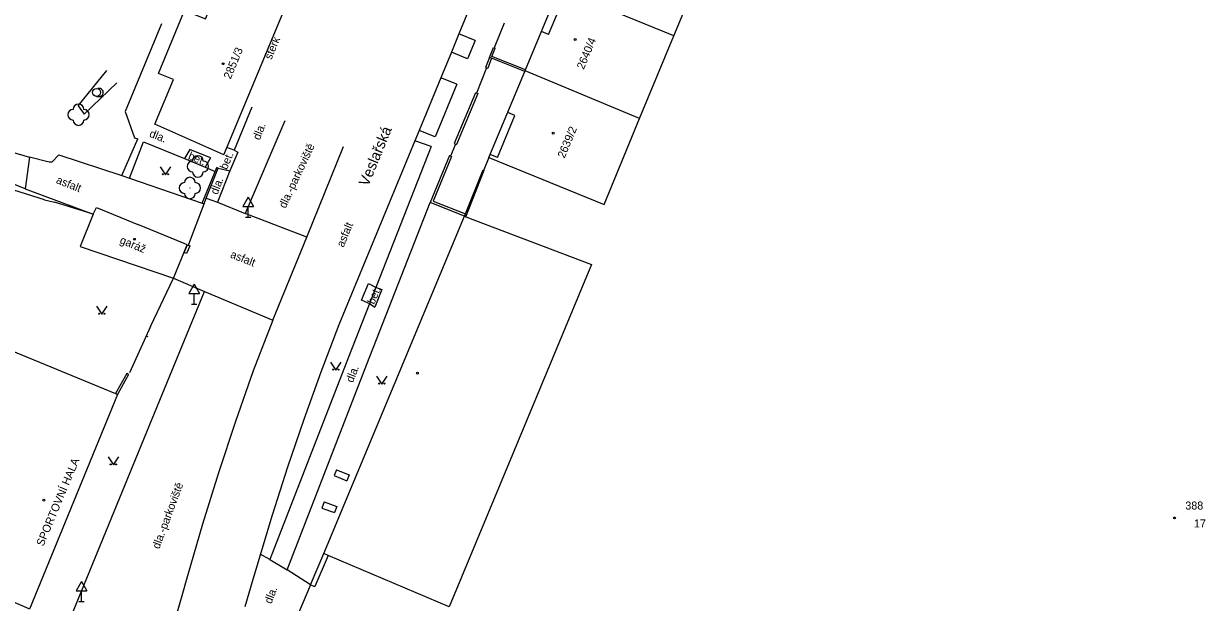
# Model space of a CAD drawing. Extents: x -584400 to -581602, y -1210894 to -1208793.
# Drawn here: x -583374.3 to -583263.6, y -1210749.1 to -1210695 of the extents above; entities that cross this region are included whole.
import ezdxf

# ---------------------------------------------------------------- set-up
doc = ezdxf.new("R2010")
doc.units = 0
for name, color, linetype in [('BUDOVY_MĚŘ', 7, 'Continuous'), ('BUDOVY_NEMĚŘ', 7, 'Continuous'), ('NÁZVY_ULIC_TOK_SMĚR', 7, 'Continuous'), ('OBVOD_PILÍŘE', 7, 'Continuous'), ('POMOC_POPIS', 7, 'Continuous'), ('ROZHRANÍ_PLOCH', 7, 'Continuous'), ('ZELEŇ', 7, 'Continuous'), ('ZN_BUDOV', 7, 'Continuous'), ('ZN_DOPLŇKOVÉ', 7, 'Continuous'), ('ZN_KULTUR', 7, 'Continuous'), ('Č_POPIS_EVID', 7, 'Continuous'), ('Č_POPIS_ORIENT', 7, 'Continuous')]:
    doc.layers.add(name, color=color, linetype=linetype)

msp = doc.modelspace()

# ---------------------------------------------------------------- linework, layer by layer
at = {"layer": 'BUDOVY_MĚŘ'}
for points in [[(-583355.51, -1210707.24), (-583348.87, -1210691.26), (-583344.69, -1210681.25), (-583344.47, -1210680.69)], [(-583327.29, -1210699.37), (-583327.26, -1210699.29), (-583324.17, -1210691.83), (-583324.11, -1210691.69)], [(-583330.68, -1210707.48), (-583327.32, -1210699.45), (-583327.29, -1210699.37)], [(-583419.13, -1210730.56), (-583417.5, -1210726.74), (-583423.55, -1210724.2), (-583417.13, -1210708.39), (-583365.65, -1210729.57), (-583365.46, -1210729.65), (-583373.7, -1210749.74), (-583373.97, -1210749.63), (-583381.84, -1210746.3), (-583382.08, -1210746.2), (-583419.13, -1210730.56)], [(-583367.74, -1210712.78), (-583367.44, -1210712.17), (-583363.58, -1210713.76)], [(-583360.23, -1210718.77), (-583358.95, -1210715.66), (-583359.23, -1210715.54), (-583363.58, -1210713.76)], [(-583345.74, -1210744.73), (-583346.15, -1210744.56), (-583332.96, -1210712.98), (-583332.85, -1210713.03)]]:
    msp.add_lwpolyline(points, dxfattribs=at)
at = {"layer": 'BUDOVY_NEMĚŘ'}
for points in [[(-583313.35, -1210696.1), (-583310.15, -1210688.36)], [(-583355.51, -1210707.24), (-583361.99, -1210704.37), (-583360.23, -1210700.2), (-583361.62, -1210699.63), (-583359.19, -1210693.72), (-583357.24, -1210694.52), (-583354.98, -1210689.24), (-583353.8, -1210689.63), (-583348.87, -1210691.26)], [(-583316.56, -1210703.85), (-583313.35, -1210696.1), (-583324.11, -1210691.69)], [(-583330.68, -1210707.48), (-583319.89, -1210711.89), (-583316.56, -1210703.85), (-583327.29, -1210699.37)], [(-583367.74, -1210712.78), (-583368.97, -1210715.81)], [(-583332.85, -1210713.03), (-583321.06, -1210717.51), (-583334.41, -1210749.53), (-583345.74, -1210744.73)], [(-583368.97, -1210715.81), (-583360.23, -1210718.77)]]:
    msp.add_lwpolyline(points, dxfattribs=at)
at = {"layer": 'OBVOD_PILÍŘE'}
msp.add_lwpolyline([(-583358.85, -1210716.12), (-583359, -1210716.48), (-583359.23, -1210716.39), (-583358.93, -1210715.66), (-583358.7, -1210715.76), (-583358.85, -1210716.12)], dxfattribs=at)
at = {"layer": 'ROZHRANÍ_PLOCH'}
for points in [[(-583325.09, -1210695.98), (-583323.48, -1210692.12), (-583324.17, -1210691.83)], [(-583332.43, -1210693.34), (-583333.5, -1210695.91)], [(-583361.34, -1210694.97), (-583364.76, -1210703.17)], [(-583333.5, -1210695.91), (-583334.19, -1210697.63)], [(-583331.98, -1210696.54), (-583333.5, -1210695.91)], [(-583325.09, -1210695.98), (-583325.76, -1210695.7)], [(-583331.98, -1210696.54), (-583332.69, -1210698.25), (-583334.19, -1210697.63)], [(-583334.19, -1210697.63), (-583335.19, -1210700.04)], [(-583335.19, -1210700.04), (-583337.2, -1210704.95)], [(-583333.67, -1210700.62), (-583335.19, -1210700.04)], [(-583333.67, -1210700.62), (-583335.71, -1210705.56), (-583337.2, -1210704.95)], [(-583352.89, -1210702.77), (-583354.55, -1210706.81)], [(-583364.76, -1210703.17), (-583363.89, -1210705.64)], [(-583329.89, -1210707.49), (-583328.25, -1210703.56), (-583328.92, -1210703.27)], [(-583349.79, -1210704.05), (-583353.52, -1210712.74)], [(-583337.2, -1210704.95), (-583337.61, -1210705.94)], [(-583381, -1210705.33), (-583373.71, -1210707.44)], [(-583365.07, -1210709.18), (-583363.58, -1210705.73)], [(-583364.36, -1210709.42), (-583363.03, -1210706.03)], [(-583363.89, -1210705.64), (-583363.58, -1210705.73)], [(-583363.03, -1210706.03), (-583359.2, -1210707.59)], [(-583337.61, -1210705.94), (-583344.73, -1210723.16), (-583346.41, -1210727.57), (-583348.01, -1210732.01), (-583349.54, -1210736.48), (-583350.99, -1210740.97), (-583352.8, -1210746.97), (-583353.54, -1210749.55)], [(-583336.08, -1210706.45), (-583337.61, -1210705.94)], [(-583370.98, -1210707.24), (-583371.62, -1210707.91)], [(-583370.98, -1210707.24), (-583365.07, -1210709.18)], [(-583358.69, -1210706.73), (-583359.2, -1210707.59)], [(-583356.75, -1210707.52), (-583358.69, -1210706.73)], [(-583354.55, -1210706.81), (-583355.23, -1210706.56)], [(-583354.19, -1210706.99), (-583354.95, -1210708.73)], [(-583354.55, -1210706.81), (-583354.19, -1210706.99)], [(-583336.08, -1210706.45), (-583343.82, -1210726.18), (-583351.19, -1210745.1)], [(-583347.74, -1210714.95), (-583344.3, -1210706.45)], [(-583329.89, -1210707.49), (-583330.56, -1210707.21)], [(-583374.12, -1210710.42), (-583381.47, -1210707.44)], [(-583373.71, -1210707.44), (-583374.12, -1210710.42)], [(-583371.87, -1210707.91), (-583373.71, -1210707.44)], [(-583371.62, -1210707.91), (-583371.87, -1210707.91)], [(-583359.2, -1210707.59), (-583357.26, -1210708.38)], [(-583356.75, -1210707.52), (-583357.26, -1210708.38)], [(-583365.07, -1210709.18), (-583364.36, -1210709.42)], [(-583364.36, -1210709.42), (-583357.54, -1210711.76), (-583357.34, -1210711.83)], [(-583357.26, -1210708.38), (-583356.32, -1210708.81)], [(-583354.95, -1210708.73), (-583356.12, -1210711.67)], [(-583356.03, -1210708.49), (-583354.95, -1210708.73)], [(-583374.12, -1210710.42), (-583367.74, -1210712.78)], [(-583357.18, -1210711.29), (-583356.12, -1210711.67)], [(-583356.12, -1210711.67), (-583353.52, -1210712.74)], [(-583347.74, -1210714.95), (-583353.52, -1210712.74)], [(-583349.58, -1210746.08), (-583342.1, -1210726.84), (-583336.19, -1210711.7)], [(-583350.91, -1210722.71), (-583347.74, -1210714.95)], [(-583360.23, -1210718.77), (-583357.31, -1210720.03)], [(-583342.62, -1210720.85), (-583341.97, -1210719.27)], [(-583341.97, -1210719.27), (-583341.31, -1210719.61)], [(-583362.21, -1210731.95), (-583357.31, -1210720.03)], [(-583357.31, -1210720.03), (-583350.91, -1210722.71)], [(-583340.7, -1210719.83), (-583341.36, -1210721.5)], [(-583341.31, -1210719.61), (-583340.7, -1210719.83)], [(-583341.78, -1210721.2), (-583342.62, -1210720.85)], [(-583341.78, -1210721.2), (-583341.36, -1210721.5)], [(-583350.91, -1210722.71), (-583352.77, -1210727.44), (-583354.43, -1210732.2), (-583356, -1210736.99), (-583357.5, -1210741.8), (-583358.93, -1210746.63), (-583360.15, -1210751.03)], [(-583370.13, -1210751.2), (-583362.21, -1210731.95)], [(-583344.96, -1210736.7), (-583345.19, -1210737.25), (-583343.99, -1210737.74)], [(-583344.96, -1210736.7), (-583343.76, -1210737.18), (-583343.99, -1210737.74)], [(-583346.12, -1210739.72), (-583346.33, -1210740.29), (-583345.15, -1210740.72)], [(-583346.12, -1210739.72), (-583344.94, -1210740.16), (-583345.15, -1210740.72)], [(-583351.19, -1210745.1), (-583352.1, -1210744.61)], [(-583351.19, -1210745.1), (-583349.58, -1210746.08)], [(-583347.4, -1210747.47), (-583349.58, -1210746.08)]]:
    msp.add_lwpolyline(points, dxfattribs=at)
at = {"layer": 'ZELEŇ'}
for points in [[(-583369.17, -1210702.66), (-583366.46, -1210699.35)], [(-583368.6, -1210703.42), (-583365.53, -1210700.51)], [(-583369.17, -1210702.66), (-583368.6, -1210703.42)]]:
    msp.add_lwpolyline(points, dxfattribs=at)
for centre in [(-583369.13, -1210703.48), (-583357.94, -1210708.32), (-583358.69, -1210710.34)]:
    msp.add_circle(centre, 0.0005, dxfattribs=at)
for centre, start, end in [((-583369.13, -1210702.98), 0, 180), ((-583369.63, -1210703.48), 90, 270), ((-583368.63, -1210703.48), 270, 90), ((-583369.13, -1210703.98), 180, 360), ((-583358.44, -1210708.32), 90, 270), ((-583357.94, -1210707.82), 0, 180), ((-583357.44, -1210708.32), 270, 90), ((-583358.69, -1210709.84), 0, 180), ((-583357.94, -1210708.82), 180, 360), ((-583359.19, -1210710.34), 90, 270), ((-583358.19, -1210710.34), 270, 90), ((-583358.69, -1210710.84), 180, 360)]:
    msp.add_arc(centre, 0.5, start, end, dxfattribs=at)
at = {"layer": 'ZN_BUDOV'}
for centre in [(-583322.6, -1210696.44), (-583355.57, -1210698.71), (-583324.65, -1210705.2), (-583363.89, -1210715.14), (-583337.38, -1210727.67), (-583372.37, -1210739.55), (-583266.45, -1210741.22)]:
    msp.add_circle(centre, 0.0875, dxfattribs=at)
at = {"layer": 'ZN_DOPLŇKOVÉ'}
for p, q in [((-583353.22, -1210711.2), (-583353.72, -1210712.07)), ((-583353.22, -1210711.2), (-583352.72, -1210712.07)), ((-583353.72, -1210712.07), (-583352.72, -1210712.07)), ((-583353.22, -1210713.07), (-583353.22, -1210712.07)), ((-583353.47, -1210713.07), (-583352.97, -1210713.07)), ((-583358.29, -1210719.33), (-583358.79, -1210720.2)), ((-583358.29, -1210719.33), (-583357.79, -1210720.2)), ((-583358.79, -1210720.2), (-583357.79, -1210720.2)), ((-583358.29, -1210721.2), (-583358.29, -1210720.2)), ((-583358.54, -1210721.2), (-583358.04, -1210721.2)), ((-583368.85, -1210747.16), (-583369.35, -1210748.03)), ((-583369.35, -1210748.03), (-583368.35, -1210748.03)), ((-583368.85, -1210747.16), (-583368.35, -1210748.03)), ((-583368.85, -1210749.03), (-583368.85, -1210748.03)), ((-583369.1, -1210749.03), (-583368.6, -1210749.03))]:
    msp.add_line(p, q, dxfattribs=at)
for points in [[(-583329.24, -1210694.91), (-583330.18, -1210697.23)], [(-583330.64, -1210698.12), (-583330.26, -1210697.19), (-583330.1, -1210697.25)], [(-583327.26, -1210699.29), (-583330.42, -1210698.02), (-583330.1, -1210697.25)], [(-583330.64, -1210698.12), (-583331.01, -1210699.05), (-583330.79, -1210699.13)], [(-583330.43, -1210698.2), (-583330.79, -1210699.13)], [(-583330.43, -1210698.2), (-583330.64, -1210698.12)], [(-583327.32, -1210699.45), (-583330.43, -1210698.2)], [(-583330.9, -1210699.09), (-583331.83, -1210701.47)], [(-583331.94, -1210701.43), (-583333.92, -1210706.19), (-583333.71, -1210706.27)], [(-583331.73, -1210701.51), (-583333.71, -1210706.27)], [(-583331.94, -1210701.43), (-583331.73, -1210701.51)], [(-583333.82, -1210706.23), (-583334.28, -1210707.35)], [(-583334.38, -1210707.31), (-583336.19, -1210711.7)], [(-583334.17, -1210707.39), (-583335.89, -1210711.58), (-583332.88, -1210712.77)], [(-583334.38, -1210707.31), (-583334.17, -1210707.39)], [(-583330.68, -1210707.48), (-583331.17, -1210708.64)], [(-583372.31, -1210711.45), (-583380.37, -1210708.92)], [(-583357.54, -1210711.76), (-583356.16, -1210708.43)], [(-583357.34, -1210711.83), (-583357.18, -1210711.29), (-583356.03, -1210708.49), (-583356.16, -1210708.43)], [(-583332.88, -1210712.77), (-583331.22, -1210708.63), (-583331.11, -1210708.67)], [(-583332.85, -1210713.03), (-583331.11, -1210708.67)], [(-583372.31, -1210711.45), (-583371.36, -1210711.68)], [(-583367.74, -1210712.78), (-583371.36, -1210711.68)], [(-583358.61, -1210715.11), (-583357.34, -1210711.83)], [(-583332.96, -1210712.98), (-583336.19, -1210711.7)], [(-583332.96, -1210712.98), (-583332.88, -1210712.77)], [(-583358.83, -1210715.69), (-583358.61, -1210715.11)], [(-583362.37, -1210723.29), (-583360.23, -1210718.77)], [(-583362.37, -1210723.29), (-583364.35, -1210727.65)], [(-583362.6, -1210724.28), (-583362.76, -1210724.2)], [(-583364.43, -1210727.78), (-583364.61, -1210727.7), (-583365.65, -1210729.57)], [(-583364.43, -1210727.78), (-583365.46, -1210729.65)], [(-583347.4, -1210747.47), (-583346.15, -1210744.56)], [(-583345.74, -1210744.73), (-583346.99, -1210747.64)], [(-583347.4, -1210747.47), (-583348.94, -1210751.15)], [(-583347.4, -1210747.47), (-583346.99, -1210747.64)]]:
    msp.add_lwpolyline(points, dxfattribs=at)
at = {"layer": 'ZN_KULTUR'}
msp.add_line((-583367.43, -1210701.77), (-583366.81, -1210701.77), dxfattribs=at)
for points in [[(-583361.48, -1210708.35), (-583360.98, -1210709.1), (-583360.48, -1210708.35)], [(-583367.45, -1210721.41), (-583366.95, -1210722.16), (-583366.45, -1210721.41)], [(-583345.53, -1210726.63), (-583345.03, -1210727.38), (-583344.53, -1210726.63)], [(-583341.2, -1210727.94), (-583340.7, -1210728.69), (-583340.2, -1210727.94)], [(-583366.36, -1210735.51), (-583365.86, -1210736.26), (-583365.36, -1210735.51)]]:
    msp.add_lwpolyline(points, dxfattribs=at)
for centre, radius in [((-583367.43, -1210701.39), 0.375), ((-583361.23, -1210709.05), 0.05), ((-583360.73, -1210709.05), 0.05), ((-583367.2, -1210722.11), 0.05), ((-583366.7, -1210722.11), 0.05), ((-583345.28, -1210727.33), 0.05), ((-583344.78, -1210727.33), 0.05), ((-583340.95, -1210728.64), 0.05), ((-583340.45, -1210728.64), 0.05), ((-583366.11, -1210736.21), 0.05), ((-583365.61, -1210736.21), 0.05)]:
    msp.add_circle(centre, radius, dxfattribs=at)
msp.add_arc((-583367.18, -1210701.39), 0.375, 249.4944, 109.0474, dxfattribs=at)

# ---------------------------------------------------------------- texts
at = {"layer": 'NÁZVY_ULIC_TOK_SMĚR'}
msp.add_text('Veslařská', height=1, rotation=67.66, dxfattribs=at).set_placement((-583341.99, -1210710.26))
at = {"layer": 'POMOC_POPIS'}
for s, rotation, p in [('štěrk', 67.1017, (-583351.06, -1210698.39)), ('dla.', 338.4121, (-583362.55, -1210705.52)), ('dla.', 68.8295, (-583352.15, -1210705.91)), ('bet.', 337.1664, (-583358.92, -1210707.61)), ('bet.', 67.1664, (-583355.23, -1210708.69)), ('dla.-parkoviště', 65.0604, (-583349.73, -1210712.3)), ('asfalt', 338.5232, (-583371.28, -1210709.87)), ('dla.', 68.8295, (-583356.11, -1210711.02)), ('asfalt', 67.3864, (-583344.3, -1210715.95)), ('garáž', 337.7458, (-583365.32, -1210715.49)), ('asfalt', 338.5232, (-583354.97, -1210716.83)), ('bet.', 67.1664, (-583341.43, -1210721.29)), ('dla.', 68.8295, (-583343.42, -1210728.61)), ('SPORTOVNÍ HALA', 67.3013, (-583372.42, -1210743.93)), ('dla.-parkoviště', 69.6642, (-583361.56, -1210744.18)), ('dla.', 68.8295, (-583351.06, -1210749.31))]:
    msp.add_text(s, height=0.75, rotation=rotation, dxfattribs=at).set_placement(p)
at = {"layer": 'Č_POPIS_EVID'}
for s, p in [('388', (-583265.44, -1210740.43)), ('17', (-583264.63, -1210742.11))]:
    msp.add_text(s, height=0.75, dxfattribs=at).set_placement(p)
at = {"layer": 'Č_POPIS_ORIENT'}
for s, rotation, p in [('2851/3', 67.37, (-583354.88, -1210700.21)), ('2640/4', 67.32, (-583321.8, -1210699.3)), ('2639/2', 67.32, (-583323.6, -1210707.61))]:
    msp.add_text(s, height=0.75, rotation=rotation, dxfattribs=at).set_placement(p)

doc.saveas('drawing.dxf')
